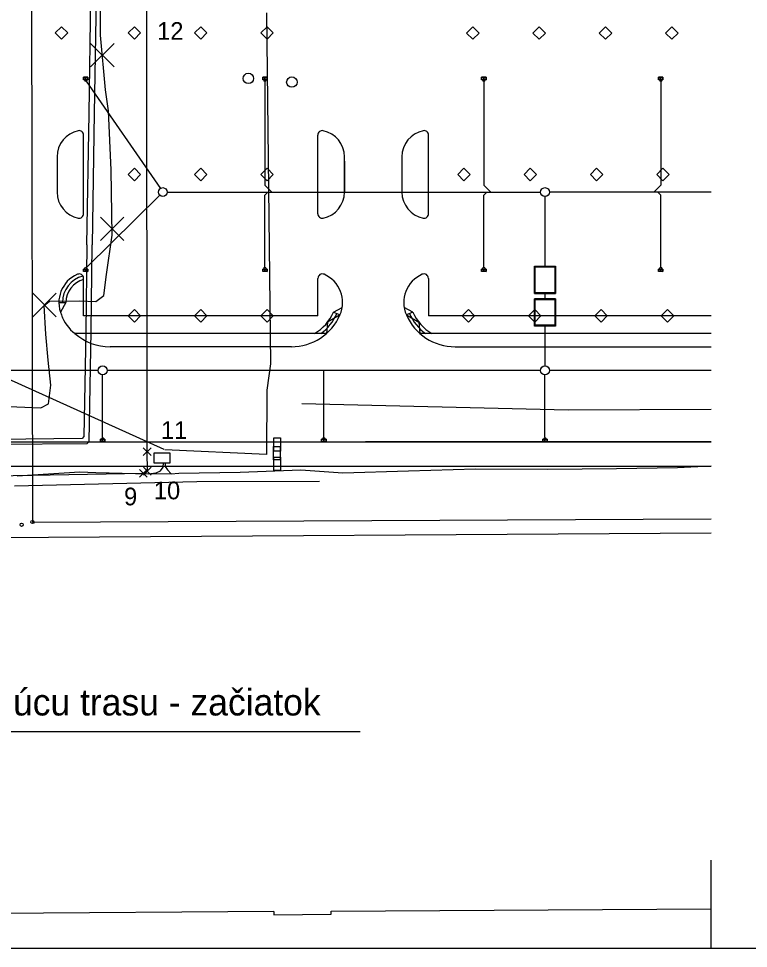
# Model space of a CAD drawing. Extents: x -264095 to -263675, y -1242370 to -1242073.
# Drawn here: x -263963.4 to -263880.9, y -1242369.5 to -1242264.4 of the extents above; entities that cross this region are included whole.
import ezdxf

# ---------------------------------------------------------------- set-up
doc = ezdxf.new("R2010")
doc.units = 0
for name, color, linetype in [('BODY', 7, 'Continuous'), ('KFA_2D_JESTVUJUCE_IS_DSP', 7, 'Continuous'), ('KFA_2D_SITUACIA_DSP', 7, 'Continuous'), ('ORANGE_KABEL_NOVA_TRASA', 7, 'Continuous'), ('POPIS', 7, 'Continuous'), ('Pripojka_NN_pre_ORANGE_vysielac_povodna_trasa', 7, 'Continuous'), ('RAM_NA_TLAC_A3_1-1000', 7, 'Continuous')]:
    doc.layers.add(name, color=color, linetype=linetype)

msp = doc.modelspace()

# ---------------------------------------------------------------- linework, layer by layer
at = {"layer": 'BODY'}
for p, q in [((-263949.32, -1242313.78), (-263948.44, -1242312.89)), ((-263948.44, -1242313.78), (-263949.32, -1242312.89)), ((-263949.29, -1242316), (-263948.41, -1242315.11)), ((-263948.41, -1242316), (-263949.29, -1242315.11)), ((-263949.76, -1242316.22), (-263948.88, -1242315.34)), ((-263948.88, -1242316.22), (-263949.76, -1242315.34))]:
    msp.add_line(p, q, dxfattribs=at)
at = {"layer": 'KFA_2D_JESTVUJUCE_IS_DSP'}
for p, q in [((-263961.97, -1242257), (-263961.85, -1242321.3)), ((-263955.44, -1242275.09), (-263955.26, -1242261.85)), ((-263954.64, -1242261.82), (-263954.86, -1242275.06)), ((-263935.39, -1242263.71), (-263934.92, -1242303.41)), ((-263955.7, -1242289.95), (-263955.44, -1242275.09)), ((-263954.86, -1242275.06), (-263955.08, -1242289.95)), ((-263955.7, -1242289.95), (-263955.83, -1242299.74)), ((-263955.22, -1242299.7), (-263955.08, -1242289.95)), ((-263955.83, -1242299.74), (-263956.02, -1242311.63)), ((-263955.44, -1242312.2), (-263955.22, -1242299.7)), ((-263934.92, -1242303.41), (-263935.36, -1242306.39)), ((-263946.96, -1242313.09), (-263966.62, -1242304.22)), ((-263935.36, -1242306.39), (-263935.4, -1242313.66)), ((-263901.29, -1242308.66), (-263931.4, -1242307.92)), ((-263885.11, -1242308.57), (-263901.29, -1242308.66)), ((-263956.22, -1242311.84), (-263967.86, -1242311.99)), ((-263956.02, -1242311.63), (-263956.22, -1242311.84)), ((-263947.21, -1242311.99), (-263947.21, -1242311.99)), ((-263934.56, -1242311.79), (-263933.81, -1242311.78)), ((-263934.55, -1242313.29), (-263934.56, -1242311.79)), ((-263933.81, -1242311.78), (-263933.8, -1242313.28)), ((-263967.84, -1242312.51), (-263955.67, -1242312.42)), ((-263955.67, -1242312.42), (-263955.44, -1242312.2)), ((-263935.4, -1242313.66), (-263946.87, -1242313.12)), ((-263934.59, -1242314.26), (-263934.58, -1242312.76)), ((-263934.58, -1242312.76), (-263933.83, -1242312.77)), ((-263933.83, -1242312.77), (-263933.84, -1242314.27)), ((-263946.29, -1242313.51), (-263948.11, -1242313.51)), ((-263948.11, -1242313.51), (-263948.11, -1242314.61)), ((-263946.29, -1242314.61), (-263946.29, -1242313.51)), ((-263934.56, -1242315.46), (-263934.55, -1242313.96)), ((-263933.8, -1242313.28), (-263934.55, -1242313.29)), ((-263934.55, -1242313.29), (-263934.55, -1242313.29)), ((-263934.55, -1242313.96), (-263933.8, -1242313.97)), ((-263933.8, -1242313.97), (-263933.81, -1242315.47)), ((-263948.11, -1242314.61), (-263946.29, -1242314.61)), ((-263947.37, -1242315.51), (-263947.08, -1242315.09)), ((-263947.08, -1242315.09), (-263947.04, -1242314.61)), ((-263946.86, -1242314.61), (-263946.83, -1242315.01)), ((-263946.83, -1242315.01), (-263946.58, -1242315.41)), ((-263933.84, -1242314.27), (-263934.59, -1242314.26)), ((-263934.59, -1242314.26), (-263934.59, -1242314.26)), ((-263919.34, -1242315.51), (-263911.76, -1242315.27)), ((-263911.76, -1242315.27), (-263903.58, -1242315.33)), ((-263903.58, -1242315.33), (-263895.84, -1242315.25)), ((-263895.84, -1242315.25), (-263888.93, -1242315.15)), ((-263888.93, -1242315.15), (-263885.11, -1242314.94)), ((-263963.59, -1242316.09), (-263956.5, -1242315.61)), ((-263956.5, -1242315.61), (-263954.68, -1242315.7)), ((-263954.68, -1242315.7), (-263948.7, -1242315.83)), ((-263948.7, -1242315.83), (-263948.46, -1242315.82)), ((-263948.46, -1242315.82), (-263947.86, -1242315.75)), ((-263948.46, -1242315.82), (-263946.15, -1242315.83)), ((-263947.86, -1242315.75), (-263947.37, -1242315.51)), ((-263946.58, -1242315.41), (-263946.15, -1242315.83)), ((-263946.15, -1242315.83), (-263945.29, -1242315.78)), ((-263945.29, -1242315.78), (-263938.38, -1242315.67)), ((-263938.38, -1242315.67), (-263931.52, -1242315.4)), ((-263933.81, -1242315.47), (-263934.56, -1242315.46)), ((-263934.56, -1242315.46), (-263934.56, -1242315.46)), ((-263931.52, -1242315.4), (-263926.77, -1242315.74)), ((-263926.77, -1242315.74), (-263919.34, -1242315.51)), ((-263963.87, -1242317.22), (-263943.25, -1242316.73)), ((-263943.25, -1242316.73), (-263929.41, -1242316.68)), ((-263961.85, -1242321.3), (-263885.11, -1242320.93)), ((-263961.85, -1242321.3), (-263961.85, -1242321.3))]:
    msp.add_line(p, q, dxfattribs=at)
for centre, radius in [((-263937.44, -1242271.12), 0.59), ((-263932.52, -1242271.54), 0.59), ((-263963.07, -1242321.61), 0.179), ((-263961.85, -1242321.3), 0.179)]:
    msp.add_circle(centre, radius, dxfattribs=at)
at = {"layer": 'KFA_2D_SITUACIA_DSP'}
for p, q in [((-263956.07, -1242270.98), (-263955.57, -1242270.98)), ((-263956.07, -1242271.27), (-263956.07, -1242270.98)), ((-263956.07, -1242270.98), (-263955.57, -1242271.27)), ((-263956.07, -1242270.98), (-263955.57, -1242271.27)), ((-263955.57, -1242270.98), (-263956.07, -1242270.98)), ((-263955.57, -1242270.98), (-263955.57, -1242271.27)), ((-263955.57, -1242271.27), (-263955.57, -1242270.98)), ((-263935.82, -1242270.98), (-263935.32, -1242270.98)), ((-263935.82, -1242271.27), (-263935.82, -1242270.98)), ((-263935.82, -1242270.98), (-263935.32, -1242271.27)), ((-263935.82, -1242270.98), (-263935.32, -1242271.27)), ((-263935.32, -1242270.98), (-263935.82, -1242270.98)), ((-263935.32, -1242270.98), (-263935.32, -1242271.27)), ((-263935.32, -1242271.27), (-263935.32, -1242270.98)), ((-263911.07, -1242270.98), (-263910.57, -1242270.98)), ((-263911.07, -1242271.27), (-263911.07, -1242270.98)), ((-263911.07, -1242270.98), (-263910.57, -1242271.27)), ((-263911.07, -1242270.98), (-263910.57, -1242271.27)), ((-263910.57, -1242270.98), (-263911.07, -1242270.98)), ((-263910.57, -1242270.98), (-263910.57, -1242271.27)), ((-263910.57, -1242271.27), (-263910.57, -1242270.98)), ((-263891.07, -1242270.98), (-263890.57, -1242270.98)), ((-263891.07, -1242271.27), (-263891.07, -1242270.98)), ((-263891.07, -1242270.98), (-263890.57, -1242271.27)), ((-263891.07, -1242270.98), (-263890.57, -1242271.27)), ((-263890.57, -1242270.98), (-263891.07, -1242270.98)), ((-263890.57, -1242270.98), (-263890.57, -1242271.27)), ((-263890.57, -1242271.27), (-263890.57, -1242270.98)), ((-263955.57, -1242271.27), (-263956.07, -1242271.27)), ((-263955.76, -1242271.45), (-263947.39, -1242283.57)), ((-263935.32, -1242271.27), (-263935.82, -1242271.27)), ((-263935.57, -1242271.47), (-263935.57, -1242283.19)), ((-263910.57, -1242271.27), (-263911.07, -1242271.27)), ((-263910.82, -1242271.47), (-263910.82, -1242283.19)), ((-263890.57, -1242271.27), (-263891.07, -1242271.27)), ((-263890.82, -1242271.47), (-263890.82, -1242283.19)), ((-263956.07, -1242286.43), (-263956.07, -1242277.53)), ((-263929.58, -1242286.43), (-263929.58, -1242277.53)), ((-263917.08, -1242286.43), (-263917.08, -1242277.53)), ((-263959.07, -1242279.98), (-263959.07, -1242283.98)), ((-263926.58, -1242283.98), (-263926.58, -1242279.98)), ((-263926.58, -1242280.48), (-263926.58, -1242283.98)), ((-263920.08, -1242279.98), (-263920.08, -1242283.98)), ((-263935.57, -1242283.19), (-263934.78, -1242283.98)), ((-263910.82, -1242283.19), (-263910.03, -1242283.98)), ((-263890.82, -1242283.19), (-263891.62, -1242283.98)), ((-263955.75, -1242292.52), (-263947.46, -1242284.33)), ((-263946.61, -1242283.98), (-263908.96, -1242283.98)), ((-263946.61, -1242283.98), (-263904.41, -1242283.98)), ((-263935.57, -1242284.34), (-263935.25, -1242283.98)), ((-263935.57, -1242292.49), (-263935.57, -1242284.34)), ((-263910.82, -1242284.34), (-263910.5, -1242283.98)), ((-263910.82, -1242292.49), (-263910.82, -1242284.34)), ((-263903.91, -1242284.48), (-263903.91, -1242292.35)), ((-263885.11, -1242283.98), (-263903.41, -1242283.98)), ((-263890.82, -1242284.34), (-263891.15, -1242283.98)), ((-263890.82, -1242292.49), (-263890.82, -1242284.34)), ((-263956.07, -1242292.69), (-263955.57, -1242292.69)), ((-263956.07, -1242292.98), (-263956.07, -1242292.69)), ((-263956.07, -1242292.69), (-263955.57, -1242292.98)), ((-263956.07, -1242292.69), (-263955.57, -1242292.98)), ((-263955.57, -1242292.69), (-263956.07, -1242292.69)), ((-263955.57, -1242292.98), (-263956.07, -1242292.98)), ((-263955.57, -1242292.69), (-263955.57, -1242292.98)), ((-263955.57, -1242292.98), (-263955.57, -1242292.69)), ((-263935.82, -1242292.69), (-263935.32, -1242292.69)), ((-263935.82, -1242292.98), (-263935.82, -1242292.69)), ((-263935.82, -1242292.69), (-263935.32, -1242292.98)), ((-263935.82, -1242292.69), (-263935.32, -1242292.98)), ((-263935.32, -1242292.69), (-263935.82, -1242292.69)), ((-263935.32, -1242292.98), (-263935.82, -1242292.98)), ((-263935.32, -1242292.69), (-263935.32, -1242292.98)), ((-263935.32, -1242292.98), (-263935.32, -1242292.69)), ((-263911.07, -1242292.69), (-263910.57, -1242292.69)), ((-263911.07, -1242292.98), (-263911.07, -1242292.69)), ((-263911.07, -1242292.69), (-263910.57, -1242292.98)), ((-263911.07, -1242292.69), (-263910.57, -1242292.98)), ((-263910.57, -1242292.69), (-263911.07, -1242292.69)), ((-263910.57, -1242292.98), (-263911.07, -1242292.98)), ((-263910.57, -1242292.69), (-263910.57, -1242292.98)), ((-263910.57, -1242292.98), (-263910.57, -1242292.69)), ((-263905.11, -1242292.35), (-263902.71, -1242292.35)), ((-263905.11, -1242295.45), (-263905.11, -1242292.35)), ((-263905.01, -1242292.45), (-263902.81, -1242292.45)), ((-263905.01, -1242295.35), (-263905.01, -1242292.45)), ((-263902.81, -1242292.45), (-263902.81, -1242295.35)), ((-263902.71, -1242292.35), (-263902.71, -1242295.45)), ((-263891.07, -1242292.69), (-263890.57, -1242292.69)), ((-263891.07, -1242292.98), (-263891.07, -1242292.69)), ((-263891.07, -1242292.69), (-263890.57, -1242292.98)), ((-263891.07, -1242292.69), (-263890.57, -1242292.98)), ((-263890.57, -1242292.69), (-263891.07, -1242292.69)), ((-263890.57, -1242292.98), (-263891.07, -1242292.98)), ((-263890.57, -1242292.69), (-263890.57, -1242292.98)), ((-263890.57, -1242292.98), (-263890.57, -1242292.69)), ((-263956.07, -1242297.98), (-263956.07, -1242293.74)), ((-263929.58, -1242297.98), (-263929.58, -1242293.74)), ((-263917.08, -1242293.74), (-263917.08, -1242297.98)), ((-263905.11, -1242295.45), (-263902.71, -1242295.45)), ((-263905.11, -1242299.15), (-263905.11, -1242296.05)), ((-263902.71, -1242296.05), (-263905.11, -1242296.05)), ((-263905.01, -1242295.35), (-263902.81, -1242295.35)), ((-263902.81, -1242296.15), (-263905.01, -1242296.15)), ((-263905.01, -1242299.05), (-263905.01, -1242296.15)), ((-263903.91, -1242295.45), (-263903.91, -1242296.05)), ((-263902.81, -1242296.15), (-263902.81, -1242299.05)), ((-263902.71, -1242296.05), (-263902.71, -1242299.15)), ((-263927.81, -1242297.56), (-263926.83, -1242297.03)), ((-263918.85, -1242297.56), (-263919.83, -1242297.03)), ((-263929.58, -1242297.98), (-263956.07, -1242297.98)), ((-263927.81, -1242297.56), (-263927.08, -1242297.88)), ((-263918.85, -1242297.56), (-263919.58, -1242297.88)), ((-263885.11, -1242297.98), (-263917.08, -1242297.98)), ((-263902.71, -1242299.15), (-263905.11, -1242299.15)), ((-263902.81, -1242299.05), (-263905.01, -1242299.05)), ((-263903.91, -1242299.15), (-263903.91, -1242303.65)), ((-263928.61, -1242299.98), (-263957.04, -1242299.98)), ((-263885.11, -1242299.98), (-263918.05, -1242299.98)), ((-263932.58, -1242301.48), (-263953.07, -1242301.48)), ((-263914.08, -1242301.48), (-263885.11, -1242301.48)), ((-263954.41, -1242304.15), (-264003.4, -1242304.15)), ((-263953.91, -1242311.74), (-263953.91, -1242304.65)), ((-263904.41, -1242304.15), (-263953.41, -1242304.15)), ((-263928.91, -1242311.74), (-263928.91, -1242304.15)), ((-263903.91, -1242311.74), (-263903.91, -1242304.65)), ((-263885.11, -1242304.15), (-263903.41, -1242304.15)), ((-263954.16, -1242311.94), (-263953.66, -1242311.94)), ((-263954.16, -1242312.23), (-263954.16, -1242311.94)), ((-263954.16, -1242311.94), (-263953.66, -1242312.23)), ((-263954.16, -1242311.94), (-263953.66, -1242312.23)), ((-263953.66, -1242311.94), (-263954.16, -1242311.94)), ((-263953.66, -1242311.94), (-263953.66, -1242312.23)), ((-263953.66, -1242312.23), (-263953.66, -1242311.94)), ((-263929.16, -1242311.94), (-263928.66, -1242311.94)), ((-263929.16, -1242312.23), (-263929.16, -1242311.94)), ((-263929.16, -1242311.94), (-263928.66, -1242312.23)), ((-263929.16, -1242311.94), (-263928.66, -1242312.23)), ((-263928.66, -1242311.94), (-263929.16, -1242311.94)), ((-263928.66, -1242311.94), (-263928.66, -1242312.23)), ((-263928.66, -1242312.23), (-263928.66, -1242311.94)), ((-263904.16, -1242311.94), (-263903.66, -1242311.94)), ((-263904.16, -1242312.23), (-263904.16, -1242311.94)), ((-263904.16, -1242311.94), (-263903.66, -1242312.23)), ((-263904.16, -1242311.94), (-263903.66, -1242312.23)), ((-263903.66, -1242311.94), (-263904.16, -1242311.94)), ((-263903.66, -1242311.94), (-263903.66, -1242312.23)), ((-263903.66, -1242312.23), (-263903.66, -1242311.94)), ((-263980.94, -1242312.23), (-263885.11, -1242312.23)), ((-263953.66, -1242312.23), (-263954.16, -1242312.23)), ((-263928.66, -1242312.23), (-263929.16, -1242312.23)), ((-263885.11, -1242312.24), (-263924.19, -1242312.23)), ((-263903.66, -1242312.23), (-263904.16, -1242312.23)), ((-264038.44, -1242314.98), (-263885.11, -1242314.98)), ((-263976.89, -1242323.14), (-263885.11, -1242322.54)), ((-263934.57, -1242365.37), (-263976.61, -1242365.64)), ((-263934.57, -1242365.37), (-263934.57, -1242365.72)), ((-263934.57, -1242365.72), (-263928.07, -1242365.67)), ((-263928.07, -1242365.32), (-263885.11, -1242365.04)), ((-263928.07, -1242365.67), (-263928.07, -1242365.32))]:
    msp.add_line(p, q, dxfattribs=at)
for points in [[(-263958.57, -1242265.28), (-263957.86, -1242265.98), (-263958.57, -1242266.69), (-263959.27, -1242265.98)], [(-263950.32, -1242265.28), (-263949.62, -1242265.98), (-263950.32, -1242266.69), (-263951.03, -1242265.98)], [(-263942.82, -1242265.28), (-263942.12, -1242265.98), (-263942.82, -1242266.69), (-263943.53, -1242265.98)], [(-263935.32, -1242265.28), (-263934.62, -1242265.98), (-263935.32, -1242266.69), (-263936.03, -1242265.98)], [(-263912.07, -1242265.28), (-263911.36, -1242265.99), (-263912.07, -1242266.69), (-263912.77, -1242265.99)], [(-263904.57, -1242265.28), (-263903.86, -1242265.99), (-263904.57, -1242266.69), (-263905.27, -1242265.99)], [(-263897.07, -1242265.28), (-263896.36, -1242265.99), (-263897.07, -1242266.69), (-263897.77, -1242265.99)], [(-263897.07, -1242265.28), (-263896.36, -1242265.99), (-263897.07, -1242266.69), (-263897.77, -1242265.99)], [(-263889.57, -1242265.28), (-263888.86, -1242265.99), (-263889.57, -1242266.69), (-263890.27, -1242265.99)], [(-263950.32, -1242281.28), (-263949.62, -1242281.98), (-263950.32, -1242282.69), (-263951.03, -1242281.98)], [(-263942.82, -1242281.28), (-263942.12, -1242281.98), (-263942.82, -1242282.69), (-263943.53, -1242281.98)], [(-263935.32, -1242281.28), (-263934.62, -1242281.98), (-263935.32, -1242282.69), (-263936.03, -1242281.98)], [(-263913.07, -1242281.28), (-263912.36, -1242281.98), (-263913.07, -1242282.69), (-263913.77, -1242281.98)], [(-263905.57, -1242281.28), (-263904.86, -1242281.98), (-263905.57, -1242282.69), (-263906.27, -1242281.98)], [(-263898.07, -1242281.28), (-263897.36, -1242281.98), (-263898.07, -1242282.69), (-263898.77, -1242281.98)], [(-263890.57, -1242281.28), (-263889.86, -1242281.98), (-263890.57, -1242282.69), (-263891.27, -1242281.98)], [(-263890.57, -1242281.28), (-263889.86, -1242281.98), (-263890.57, -1242282.69), (-263891.27, -1242281.98)], [(-263949.62, -1242297.98), (-263950.32, -1242297.28), (-263951.03, -1242297.98), (-263950.32, -1242298.69)], [(-263942.12, -1242297.98), (-263942.82, -1242297.28), (-263943.53, -1242297.98), (-263942.82, -1242298.69)], [(-263934.62, -1242297.98), (-263935.32, -1242297.28), (-263936.03, -1242297.98), (-263935.32, -1242298.69)], [(-263912.57, -1242297.28), (-263911.86, -1242297.98), (-263912.57, -1242298.69), (-263913.27, -1242297.98)], [(-263905.07, -1242297.28), (-263904.36, -1242297.98), (-263905.07, -1242298.69), (-263905.77, -1242297.98)], [(-263897.57, -1242297.28), (-263896.86, -1242297.98), (-263897.57, -1242298.69), (-263898.27, -1242297.98)], [(-263890.07, -1242297.28), (-263889.36, -1242297.98), (-263890.07, -1242298.69), (-263890.77, -1242297.98)], [(-263890.07, -1242297.28), (-263889.36, -1242297.98), (-263890.07, -1242298.69), (-263890.77, -1242297.98)]]:
    msp.add_lwpolyline(points, close=True, dxfattribs=at)
for points in [[(-263958.86, -1242296.48), (-263958.06, -1242296.48), (-263958.69, -1242297.56)], [(-263927.08, -1242297.88), (-263928.51, -1242298.71), (-263928.61, -1242299.98)], [(-263919.58, -1242297.88), (-263918.15, -1242298.71), (-263918.05, -1242299.98)]]:
    msp.add_lwpolyline(points, dxfattribs=at)
for centre, radius in [((-263955.82, -1242271.37), 0.1), ((-263935.57, -1242271.37), 0.1), ((-263910.82, -1242271.37), 0.1), ((-263890.82, -1242271.37), 0.1), ((-263947.11, -1242283.98), 0.5), ((-263903.91, -1242283.98), 0.5), ((-263955.82, -1242292.59), 0.1), ((-263935.57, -1242292.59), 0.1), ((-263910.82, -1242292.59), 0.1), ((-263890.82, -1242292.59), 0.1), ((-263953.91, -1242304.15), 0.5), ((-263903.91, -1242304.15), 0.5), ((-263953.91, -1242311.84), 0.1), ((-263928.91, -1242311.84), 0.1), ((-263903.91, -1242311.84), 0.1)]:
    msp.add_circle(centre, radius, dxfattribs=at)
for centre, radius, start, end in [((-263956.07, -1242279.98), 3, 101.537, 180), ((-263956.57, -1242277.53), 0.5, 0, 101.537), ((-263929.08, -1242277.53), 0.5, 78.463, 180), ((-263929.58, -1242279.98), 3, 0, 78.463), ((-263917.08, -1242279.98), 3, 101.537, 180), ((-263917.58, -1242277.53), 0.5, 0, 101.537), ((-263956.07, -1242283.98), 3, 180, 258.463), ((-263929.58, -1242283.98), 3, 281.537, 0), ((-263917.08, -1242283.98), 3, 180, 258.463), ((-263956.57, -1242286.43), 0.5, 258.463, 0), ((-263929.08, -1242286.43), 0.5, 180, 281.537), ((-263917.58, -1242286.43), 0.5, 258.463, 0), ((-263955.36, -1242296.48), 3.5, 113.7599, 203.5782), ((-263955.36, -1242296.48), 3.1, 104.5457, 180), ((-263955.36, -1242296.48), 2.7, 105.2176, 180), ((-263956.57, -1242293.74), 0.5, 0, 113.7599), ((-263929.08, -1242293.74), 0.5, 66.2401, 180), ((-263930.29, -1242296.48), 3.5, 336.4218, 66.2401), ((-263916.37, -1242296.48), 3.5, 113.7599, 203.5782), ((-263917.58, -1242293.74), 0.5, 0, 113.7599), ((-263954.44, -1242296.49), 4.35, 198.7173, 233.4513), ((-263932.58, -1242295.48), 6, 270, 336.4218), ((-263932.58, -1242295.48), 5.2, 300.0733, 336.4218), ((-263932.58, -1242295.48), 5.6, 306.5275, 336.4218), ((-263914.08, -1242295.48), 6, 203.5782, 270), ((-263914.08, -1242295.48), 5.6, 203.5782, 233.4725), ((-263914.08, -1242295.48), 5.2, 203.5782, 239.9267), ((-263953.07, -1242295.48), 6, 228.5904, 270)]:
    msp.add_arc(centre, radius, start, end, dxfattribs=at)
at = {"layer": 'ORANGE_KABEL_NOVA_TRASA'}
msp.add_lwpolyline([(-264024.49, -1242318.06), (-264024.03, -1242317.04), (-264023.37, -1242316.88), (-264019.94, -1242316.82), (-264007.09, -1242316.55), (-263992.06, -1242316.47), (-263977.15, -1242316.36), (-263964.02, -1242316.05), (-263949.32, -1242315.78), (-263948.85, -1242315.55), (-263948.88, -1242313.34), (-263948.91, -1242263.22), (-263949.46, -1242259.66), (-263949.68, -1242246.61), (-263949.38, -1242192.16), (-263951.11, -1242181.25), (-263952.04, -1242175.2)], dxfattribs=at)
at = {"layer": 'POPIS'}
msp.add_line((-264007.78, -1242345), (-263924.8, -1242345), dxfattribs=at)
at = {"layer": 'Pripojka_NN_pre_ORANGE_vysielac_povodna_trasa'}
for p, q in [((-263955.27, -1242269.83), (-263952.61, -1242267.18)), ((-263952.61, -1242269.83), (-263955.27, -1242267.18)), ((-263954.17, -1242289.46), (-263951.52, -1242286.8)), ((-263951.52, -1242289.46), (-263954.17, -1242286.8)), ((-263961.82, -1242298.09), (-263959.17, -1242295.43)), ((-263959.17, -1242298.09), (-263961.82, -1242295.43))]:
    msp.add_line(p, q, dxfattribs=at)
msp.add_lwpolyline([(-263965.43, -1242308.21), (-263960.91, -1242308.38), (-263960.04, -1242307.93), (-263959.77, -1242305.83), (-263960.07, -1242303), (-263960.34, -1242300.07), (-263960.54, -1242296.8), (-263959.91, -1242296.33), (-263956.52, -1242296.3), (-263954.69, -1242296.34), (-263953.77, -1242295.68), (-263953.47, -1242293.29), (-263952.83, -1242288.84), (-263952.96, -1242281.51), (-263953.24, -1242274.78), (-263953.58, -1242272.42), (-263954.15, -1242266.22), (-263954.18, -1242259.42)], dxfattribs=at)
at = {"layer": 'RAM_NA_TLAC_A3_1-1000'}
msp.add_line((-263885.11, -1242369.53), (-263885.11, -1242359.53), dxfattribs=at)
msp.add_lwpolyline([(-264095.11, -1242072.53), (-263675.11, -1242072.53), (-263675.11, -1242369.53), (-264095.11, -1242369.53)], close=True, dxfattribs=at)

# ---------------------------------------------------------------- texts
at = {"layer": 'BODY'}
for s, p in [('12', (-263947.75, -1242266.76)), ('11', (-263947.32, -1242311.9)), ('9', (-263951.49, -1242319.41)), ('10', (-263948.12, -1242318.73))]:
    msp.add_text(s, height=2, dxfattribs=at).set_placement(p)
at = {"layer": 'POPIS'}
msp.add_text('bod napojenia na jestvujúcu trasu - začiatok', height=3, dxfattribs=at).set_placement((-264007.32, -1242343.18))

doc.saveas('drawing.dxf')
